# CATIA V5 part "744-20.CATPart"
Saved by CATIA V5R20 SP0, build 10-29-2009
Part number: 744-20
Revision: TUTTO
Definition: NON CONOSCIUTO
Nomenclature: 744-20
Source: Unknown
Bounding box of the stored display mesh (mm): x -20 to 20, y -21 to 20, z -23 to 20
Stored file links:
  C:\Users\Utente\Desktop\IO LAVORO\3D X SITO CF\X SITO\744\744-20.CATPart
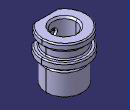
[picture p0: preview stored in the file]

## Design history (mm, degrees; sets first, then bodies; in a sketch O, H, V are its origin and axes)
Body1 "744-20 sol1" (main body)
  Solid1: solid without history
Body2 "IDV1M8_Ingrassatore-1"
  Solid2: solid without history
